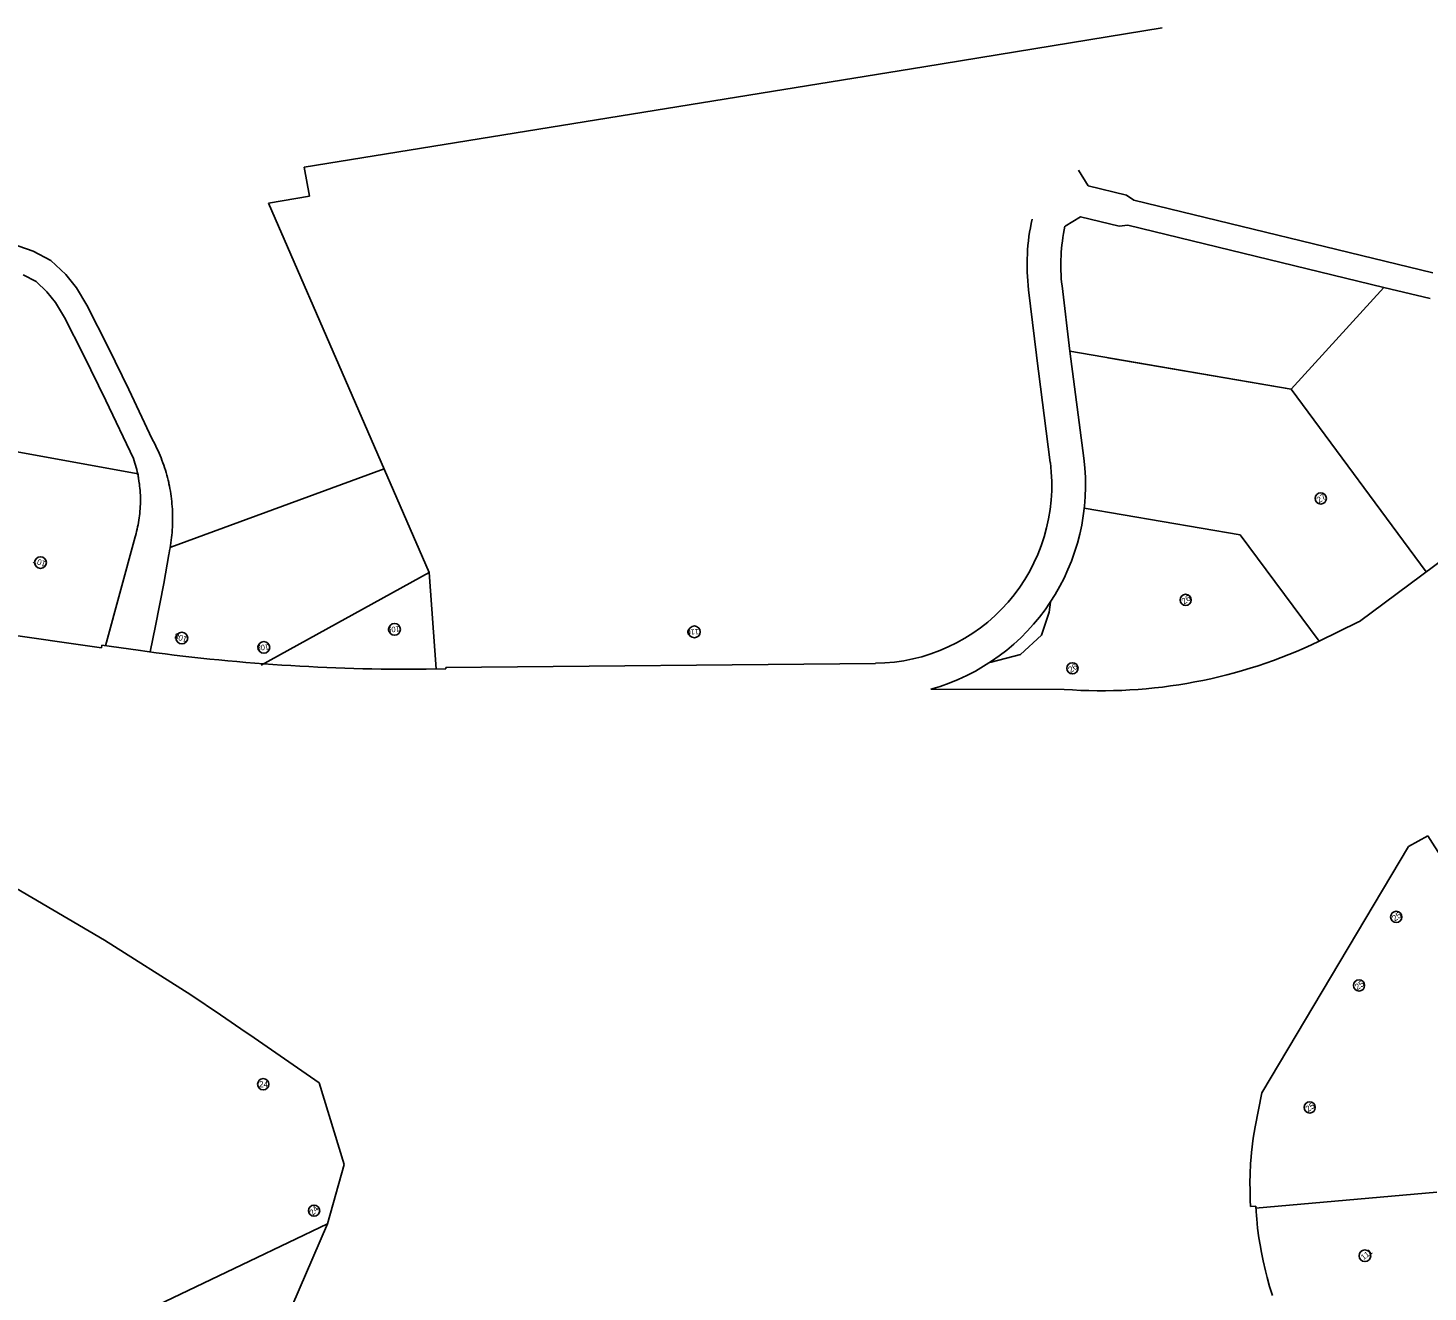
# Model space of a CAD drawing. Extents: x 1601085 to 1622464, y 1082944 to 1103437.
# Drawn here: x 1609043 to 1611786, y 1093415 to 1095892 of the extents above; entities that cross this region are included whole.
import ezdxf

# ---------------------------------------------------------------- set-up
doc = ezdxf.new("R2010")
doc.units = 0
for name, color, linetype in [('Level 14', 7, 'Continuous'), ('Level 31', 7, 'Continuous'), ('Level 9', 7, 'Continuous')]:
    doc.layers.add(name, color=color, linetype=linetype)

msp = doc.modelspace()

# ---------------------------------------------------------------- linework, layer by layer
at = {"layer": 'Level 14'}
for p, q in [((1611265, 1095892.2), (1610798, 1095816.2)), ((1610798, 1095816.2), (1609583.8, 1095619.4)), ((1609583.8, 1095619.4), (1609594, 1095562.3)), ((1609594, 1095562.3), (1609513.7, 1095549.1)), ((1609513.7, 1095549.1), (1609828.7, 1094825.3)), ((1611517.8, 1095184), (1611699.9, 1095383.8)), ((1611517.8, 1095184), (1611084.5, 1095258.7)), ((1611158.8, 1095245.9), (1611517.8, 1095184)), ((1611782.8, 1094826.5), (1611517.8, 1095184)), ((1608950.6, 1095073.9), (1609258.4, 1095018.5)), ((1609740.3, 1095028.3), (1609322.7, 1094874.7)), ((1609258.4, 1095018.5), (1609259.3, 1095007.2)), ((1611418.2, 1094898.6), (1611112.2, 1094951.4)), ((1611572.7, 1094690.3), (1611418.2, 1094898.6)), ((1609499.7, 1094643.2), (1609828.7, 1094825.3)), ((1609828.7, 1094825.3), (1609842.5, 1094635.9)), ((1611043.5, 1094747.3), (1611046.2, 1094767.1)), ((1611028.5, 1094702.2), (1611043.5, 1094747.3)), ((1610987.5, 1094664.5), (1611028.5, 1094702.2)), ((1610928, 1094649.2), (1610930.2, 1094649.3)), ((1610930.2, 1094649.3), (1610987.5, 1094664.5)), ((1611803.7, 1093610.9), (1611448.2, 1093579.2)), ((1609629.5, 1093548.3), (1609476.9, 1093475.5)), ((1609476.9, 1093475.5), (1609049.5, 1093271.6))]:
    msp.add_line(p, q, dxfattribs=at)
at = {"layer": 'Level 31'}
for p, q in [((1611651.7, 1094729.1), (1613041.3, 1095762)), ((1611120.3, 1095583.1), (1611101.6, 1095613.4)), ((1611195.6, 1095564.8), (1611120.3, 1095583.1)), ((1611209.7, 1095554.6), (1611195.6, 1095564.8)), ((1611795.7, 1095412), (1611209.7, 1095554.6)), ((1611105.4, 1095521.8), (1611074.9, 1095503.5)), ((1611180.7, 1095503.5), (1611105.4, 1095521.8)), ((1611197.9, 1095506), (1611180.7, 1095503.5)), ((1611699.9, 1095383.8), (1611197.9, 1095506)), ((1609053, 1095454.5), (1608977.9, 1095480.6)), ((1609087.6, 1095436.3), (1609053, 1095454.5)), ((1609116.6, 1095409.1), (1609087.6, 1095436.3)), ((1609033.1, 1095408.5), (1609058.4, 1095395.2)), ((1609137.7, 1095382.8), (1609116.6, 1095409.1)), ((1609058.4, 1095395.2), (1609079.8, 1095375.1)), ((1609157.9, 1095349.1), (1609137.7, 1095382.8)), ((1611019, 1095250.8), (1611003.6, 1095379)), ((1611084.5, 1095258.7), (1611069.1, 1095386.9)), ((1611699.9, 1095383.8), (1611790.4, 1095361.7)), ((1609079.8, 1095375.1), (1609096.5, 1095354.2)), ((1609096.5, 1095354.2), (1609114.1, 1095324.8)), ((1609114.1, 1095324.8), (1609151.5, 1095251.7)), ((1609200.3, 1095265.6), (1609157.9, 1095349.1)), ((1609151.5, 1095251.7), (1609195.4, 1095162.3)), ((1609240.5, 1095183.9), (1609200.3, 1095265.6)), ((1611046.1, 1095040.8), (1611019, 1095250.2)), ((1611111.6, 1095049.2), (1611084.5, 1095258.7)), ((1609195.4, 1095162.3), (1609249.4, 1095048.2)), ((1609286.1, 1095086.4), (1609240.5, 1095183.9)), ((1609252.5, 1094894.9), (1609194.8, 1094681.5)), ((1609308.8, 1094803.5), (1609318.4, 1094860.5)), ((1609292.4, 1094720.6), (1609308.8, 1094803.5)), ((1609282.3, 1094669.3), (1609292.4, 1094720.6)), ((1611650.3, 1094728.1), (1611572.7, 1094690.3)), ((1611651.7, 1094729.1), (1611650.3, 1094728.1)), ((1608893.4, 1094718.9), (1609186.6, 1094677.6)), ((1609186.6, 1094677.6), (1609187.3, 1094682.6)), ((1609187.3, 1094682.6), (1609258.6, 1094672.5)), ((1610703.3, 1094647), (1609861.5, 1094639)), ((1609861.5, 1094639), (1609861.5, 1094636)), ((1609861.5, 1094636), (1609822.9, 1094635.7)), ((1610811.6, 1094596.3), (1611073.4, 1094595.8)), ((1611786.2, 1094309), (1611748.2, 1094288)), ((1611748.2, 1094288), (1611460.9, 1093805.2)), ((1609020.4, 1094205.8), (1609192.7, 1094104.7)), ((1609192.7, 1094104.7), (1609361.6, 1093997.5)), ((1609361.6, 1093997.5), (1609419.8, 1093957.8)), ((1609419.8, 1093957.8), (1609470.3, 1093923.7)), ((1609470.3, 1093923.7), (1609477.3, 1093918.9)), ((1609477.3, 1093918.9), (1609613.3, 1093824.8)), ((1609613.3, 1093824.8), (1609662.5, 1093664.8)), ((1609662.5, 1093664.8), (1609629.5, 1093548.3)), ((1611438.6, 1093582.6), (1611448.6, 1093583)), ((1609629.5, 1093548.3), (1609542, 1093346.4))]:
    msp.add_line(p, q, dxfattribs=at)
for points in [[(1609286.1, 1095086.4), (1609288.5, 1095081.9), (1609290.9, 1095077.4), (1609293.1, 1095072.9), (1609295.3, 1095068.3), (1609297.5, 1095063.7), (1609299.5, 1095059), (1609301.5, 1095054.3), (1609303.4, 1095049.6), (1609305.2, 1095044.9), (1609307, 1095040.1), (1609308.7, 1095035.3), (1609310.3, 1095030.5), (1609311.8, 1095025.7), (1609313.3, 1095020.8), (1609314.7, 1095015.9), (1609316, 1095011), (1609317.2, 1095006.1), (1609318.3, 1095001.1), (1609318.8, 1094999), (1609319.8, 1094994.5), (1609320.7, 1094989.5), (1609321.6, 1094984.5), (1609322.4, 1094979.4), (1609323.1, 1094974.4), (1609323.8, 1094969.4), (1609324.4, 1094964.3), (1609324.8, 1094959.3), (1609325.3, 1094954.2), (1609325.6, 1094949.1), (1609325.8, 1094944.1), (1609326, 1094939), (1609326.1, 1094933.9), (1609326.1, 1094928.8), (1609326, 1094923.7), (1609325.9, 1094918.7), (1609325.7, 1094913.6), (1609325.4, 1094908.5), (1609325, 1094903.4), (1609324.5, 1094898.4), (1609323.9, 1094893.3), (1609323.3, 1094888.3), (1609322.6, 1094883.2), (1609321.8, 1094878.2), (1609321, 1094873.2), (1609320, 1094868.2), (1609319, 1094863.2), (1609318.4, 1094860.5)], [(1609249.4, 1095048.2), (1609250.8, 1095043.9), (1609252.2, 1095039.6), (1609253.4, 1095035.3), (1609254.6, 1095031), (1609255.7, 1095026.7), (1609256.8, 1095022.3), (1609257.7, 1095017.9), (1609258.6, 1095013.5), (1609259.4, 1095009.1), (1609260.1, 1095004.7), (1609260.7, 1095000.3), (1609260.9, 1094999), (1609261.4, 1094994.5), (1609261.9, 1094990.1), (1609262.3, 1094985.6), (1609262.6, 1094981.1), (1609262.8, 1094976.7), (1609262.9, 1094972.2), (1609263, 1094967.7), (1609263, 1094963.2), (1609262.9, 1094958.7), (1609262.7, 1094954.2), (1609262.4, 1094949.8), (1609262.1, 1094945.3), (1609261.6, 1094940.8), (1609261.1, 1094936.4), (1609260.6, 1094931.9), (1609259.9, 1094927.5), (1609259.2, 1094923.1), (1609258.4, 1094918.7), (1609257.5, 1094914.3), (1609256.5, 1094909.9), (1609255.4, 1094905.5), (1609254.3, 1094901.2), (1609253.1, 1094896.9), (1609252.5, 1094894.9)], [(1612209.8, 1093638.6), (1612197.8, 1093657.9), (1612172.2, 1093698.3), (1612144, 1093742.5), (1612115.5, 1093787.5), (1612088.3, 1093830.5), (1612061.2, 1093873.4), (1612033.2, 1093917.6), (1612005.8, 1093961.5), (1611978.4, 1094004.8), (1611950.5, 1094048.8), (1611922.6, 1094092.6), (1611895.6, 1094135.4), (1611868.8, 1094178), (1611841.9, 1094220.6), (1611814.8, 1094263.7), (1611786.2, 1094309)], [(1611460.9, 1093805.2), (1611447.2, 1093738.9), (1611443.6, 1093716.3), (1611440.2, 1093688.1), (1611439.4, 1093680.1), (1611438.3, 1093665.8), (1611437.4, 1093646.8), (1611437.2, 1093628.7), (1611437.4, 1093615.2), (1611438, 1093595.1), (1611438.6, 1093582.6)], [(1611448.6, 1093583), (1611448.6, 1093582.8), (1611450, 1093563.9), (1611450.5, 1093558.1), (1611452.4, 1093540.2), (1611454.9, 1093521.4), (1611457, 1093507.5), (1611459.9, 1093492.5), (1611463.3, 1093475.9), (1611467.5, 1093456.6), (1611470.8, 1093443.2), (1611475.9, 1093425.6), (1611481.7, 1093408.2)]]:
    msp.add_lwpolyline(points, dxfattribs=at)
for centre, radius, start, end in [((1611415.6, 1095428.2), 415, 167.5357, 186.8032), ((1611415.6, 1095428.2), 349, 167.5357, 186.8032), ((1610700, 1094996), 349, 270.5415, 7.3718), ((1610700, 1094996), 415, 285.6033, 7.3718), ((1609787.1, 1098425.2), 3789.7, 261.9834, 270.5415), ((1611145.1, 1095583.8), 990.6, 265.8491, 295.5724)]:
    msp.add_arc(centre, radius, start, end, dxfattribs=at)
at = {"layer": 'Level 9'}
for centre, radius in [((1611576, 1094970.1), 11), ((1609067.1, 1094844.5), 11.5), ((1611311.3, 1094771.4), 11), ((1609761, 1094713.6), 11.5), ((1609344.1, 1094696.4), 11.5), ((1610348.5, 1094708.7), 11.5), ((1609504.8, 1094678.2), 11.5), ((1611089.4, 1094637.3), 11), ((1611724, 1094150.1), 11), ((1611651.1, 1094015.7), 11), ((1609503.5, 1093822.1), 11), ((1611554.4, 1093776.6), 11), ((1609603.3, 1093574.3), 11), ((1611662.5, 1093485.9), 11.5)]:
    msp.add_circle(centre, radius, dxfattribs=at)

# ---------------------------------------------------------------- texts
for s, height, rotation, p in [('27', 12, 35.0468, (1611572.9, 1094960.6)), ('107', 11.4, 160.7681, (1609078.9, 1094846.4)), ('26', 12, 35.0468, (1611308.2, 1094761.8)), ('108', 11.4, 160.7681, (1609355.9, 1094698.3)), ('109', 10.83, 182.696, (1609770.7, 1094719.5)), ('110', 10.83, 182.696, (1610357.2, 1094714.5)), ('108', 10.83, 182.696, (1609514.6, 1094684.1)), ('26', 12, 35.0468, (1611086.2, 1094627.7)), ('25', 12, 35.0468, (1611720.9, 1094140.6)), ('25', 12, 35.0468, (1611648, 1094006.2)), ('24', 12, 0.7452, (1609495.5, 1093816)), ('25', 12, 35.0468, (1611551.2, 1093767.1)), ('24', 12, 48.1297, (1609601.3, 1093564)), ('111', 10.83, 37.2466, (1611659.9, 1093477.2))]:
    msp.add_text(s, height=height, rotation=rotation, dxfattribs=at).set_placement(p)

doc.saveas('drawing.dxf')
